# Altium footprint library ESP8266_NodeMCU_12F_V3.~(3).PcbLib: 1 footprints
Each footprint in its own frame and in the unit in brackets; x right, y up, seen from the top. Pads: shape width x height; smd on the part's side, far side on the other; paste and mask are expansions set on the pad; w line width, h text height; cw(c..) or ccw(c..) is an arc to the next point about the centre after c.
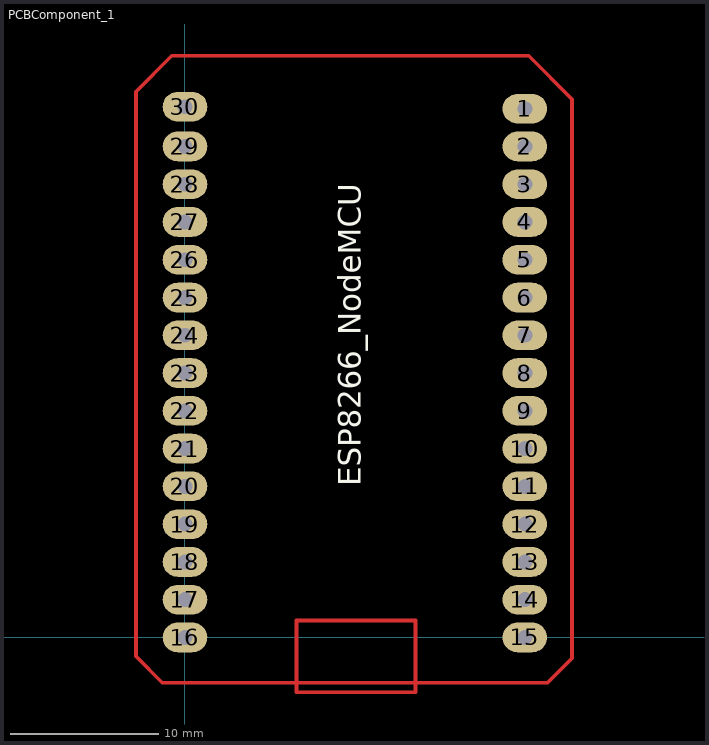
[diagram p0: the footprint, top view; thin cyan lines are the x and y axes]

## PCBComponent_1 [mm]
pads (30):
  oval 3x2 hole 1 paste+0 mask+0.102: 1(22.86,35.56) 2(22.86,33.02) 3(22.86,30.48) 4(22.86,27.94) 5(22.86,25.4) 6(22.86,22.86) 7(22.86,20.32) 8(22.86,17.78) 9(22.86,15.24) 10(22.86,12.7) 11(22.86,10.16) 12(22.86,7.62) 13(22.86,5.08) 14(22.86,2.54) 15(22.86,0) 16(0,0) 17(0,2.54) 18(0,5.08) 19(0,7.62) 20(0,10.16) 21(0,12.7) 22(0,15.24) 23(0,17.78) 24(0,20.32) 25(0,22.86) 26(0,25.4) 27(0,27.94) 28(0,30.48) 29(0,33.02) 30(0,35.687)
Top Layer:
  lines w0.254: -3.302,-1.27 -1.524,-3.048 24.384,-3.048 26.035,-1.397 26.035,36.195 23.114,39.116 -0.889,39.116 -3.302,36.703 -3.302,-1.27 ; 7.493,-3.683 7.493,1.143 15.494,1.143 15.494,-3.683 7.493,-3.683
Top Overlay:
  text "ESP8266_NodeMCU" at 11.811,10.16 h1.52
